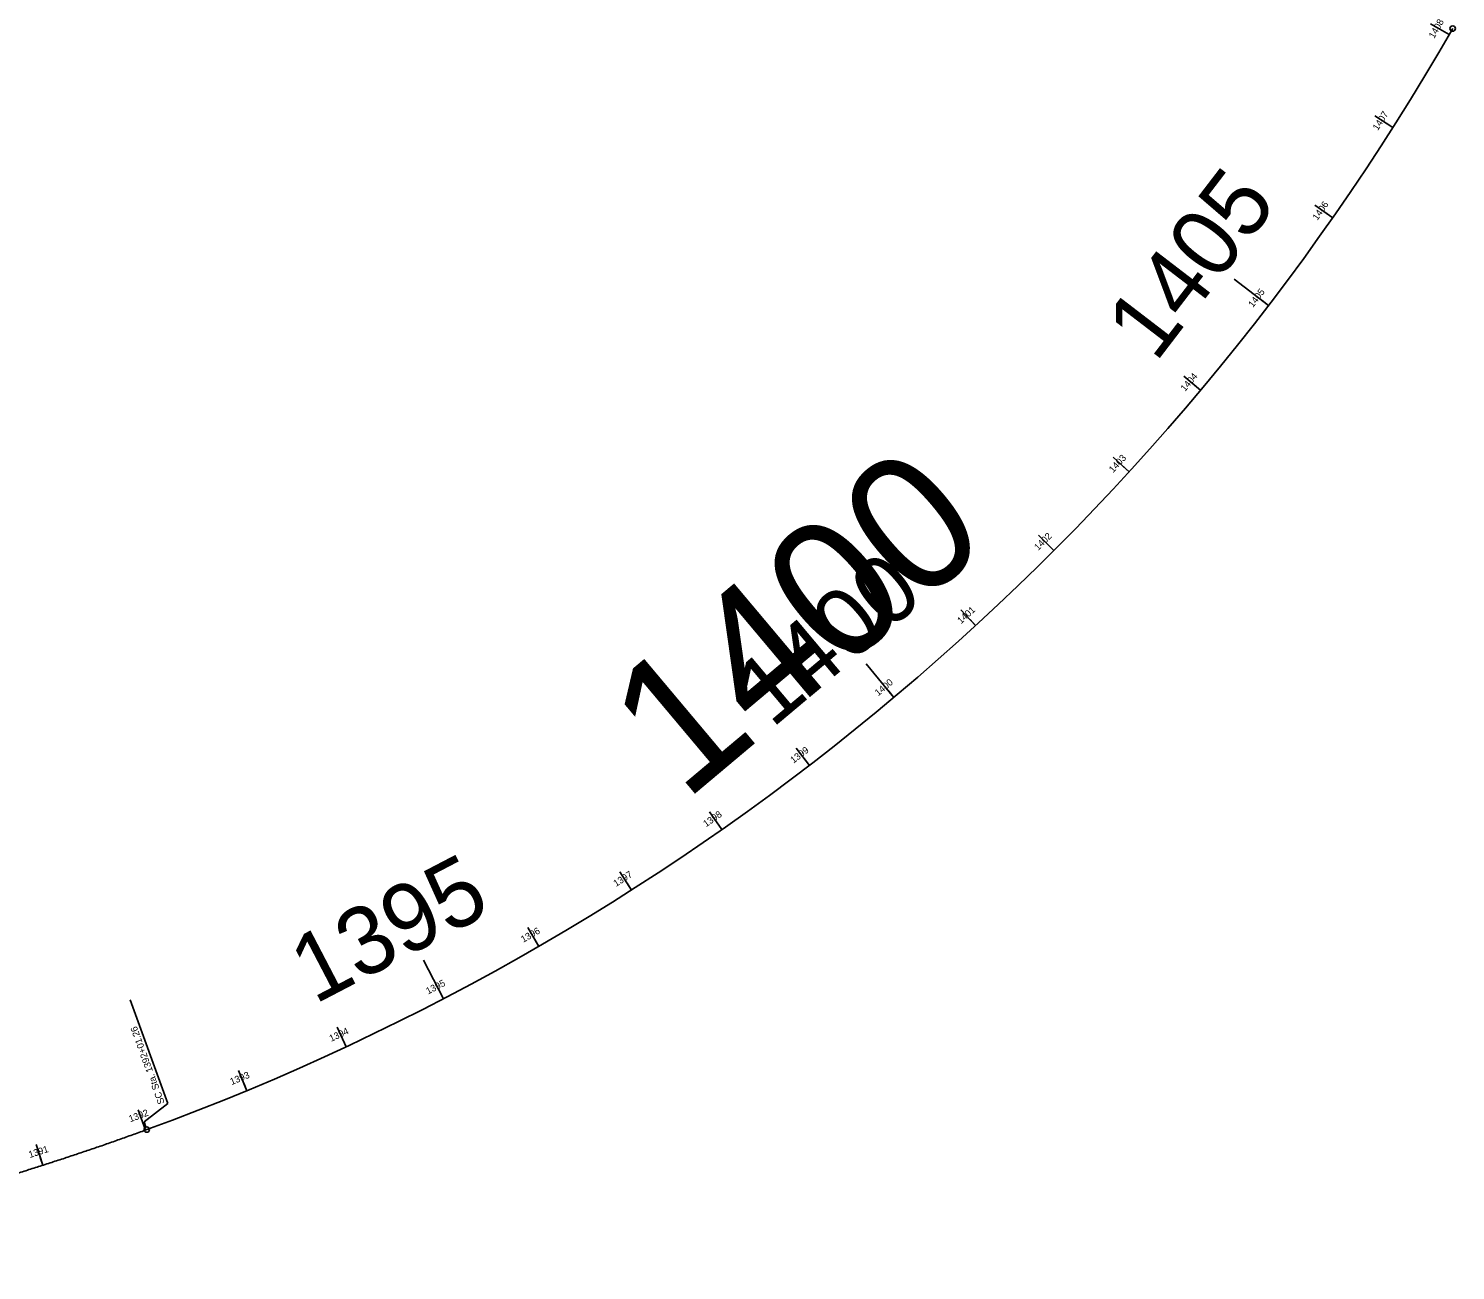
# Model space of a CAD drawing. Extents: x 1281433 to 1457183, y 526241 to 603611.
# Drawn here: x 1397548 to 1398861, y 573059 to 574202 of the extents above; entities that cross this region are included whole.
import ezdxf

# ---------------------------------------------------------------- set-up
doc = ezdxf.new("R2010")
doc.units = 0
for name, color, linetype in [('Level 20', 7, 'Continuous'), ('Level 21', 7, 'Continuous'), ('Level 22', 7, 'Continuous'), ('Level 4', 7, 'Continuous'), ('Level 6', 7, 'Continuous'), ('Level 7', 7, 'Continuous')]:
    doc.layers.add(name, color=color, linetype=linetype)

msp = doc.modelspace()

# ---------------------------------------------------------------- linework, layer by layer
at = {"layer": 'Level 20'}
msp.add_arc((1396870.1, 575341.1), 2291.8, 290.0679, 330.1964, dxfattribs=at)
msp.add_spline([(1397210.2, 573058.8), (1397216.3, 573060.4), (1397222.4, 573061.9), (1397228.5, 573063.5), (1397234.6, 573065), (1397240.6, 573066.6), (1397246.7, 573068.1), (1397252.8, 573069.7), (1397258.9, 573071.2), (1397265, 573072.8), (1397271.1, 573074.4), (1397277.2, 573075.9), (1397283.3, 573077.5), (1397289.3, 573079), (1397295.4, 573080.6), (1397301.5, 573082.2), (1397307.6, 573083.8), (1397313.7, 573085.3), (1397319.8, 573086.9), (1397325.8, 573088.5), (1397331.9, 573090.1), (1397338, 573091.7), (1397344.1, 573093.3), (1397350.1, 573094.9), (1397356.2, 573096.5), (1397362.3, 573098.1), (1397368.4, 573099.7), (1397374.4, 573101.4), (1397380.5, 573103), (1397386.6, 573104.6), (1397392.6, 573106.3), (1397398.7, 573107.9), (1397404.8, 573109.6), (1397410.8, 573111.3), (1397416.9, 573112.9), (1397422.9, 573114.6), (1397429, 573116.3), (1397435, 573118), (1397441.1, 573119.7), (1397447.1, 573121.4), (1397453.2, 573123.1), (1397459.2, 573124.9), (1397465.2, 573126.6), (1397471.3, 573128.4), (1397477.3, 573130.1), (1397483.3, 573131.9), (1397489.4, 573133.7), (1397495.4, 573135.5), (1397501.4, 573137.3), (1397507.4, 573139.1), (1397513.4, 573140.9), (1397519.5, 573142.7), (1397525.5, 573144.6), (1397531.5, 573146.4), (1397537.5, 573148.3), (1397543.5, 573150.2), (1397549.5, 573152.1), (1397555.4, 573154), (1397561.4, 573155.9), (1397567.4, 573157.8), (1397573.4, 573159.8), (1397579.4, 573161.7), (1397585.3, 573163.7), (1397591.3, 573165.7), (1397597.2, 573167.7), (1397603.2, 573169.7), (1397609.1, 573171.7), (1397615.1, 573173.7), (1397621, 573175.8), (1397627, 573177.9), (1397632.9, 573180), (1397638.8, 573182.1), (1397644.7, 573184.2), (1397650.6, 573186.3), (1397656.5, 573188.5)], degree=3, dxfattribs=at)
at = {"layer": 'Level 21'}
msp.add_arc((1396870.1, 575341.1), 2291.8, 290.0679, 330.1964, dxfattribs=at)
msp.add_spline([(1397210.2, 573058.8), (1397216.3, 573060.4), (1397222.4, 573061.9), (1397228.5, 573063.5), (1397234.6, 573065), (1397240.6, 573066.6), (1397246.7, 573068.1), (1397252.8, 573069.7), (1397258.9, 573071.2), (1397265, 573072.8), (1397271.1, 573074.4), (1397277.2, 573075.9), (1397283.3, 573077.5), (1397289.3, 573079), (1397295.4, 573080.6), (1397301.5, 573082.2), (1397307.6, 573083.8), (1397313.7, 573085.3), (1397319.8, 573086.9), (1397325.8, 573088.5), (1397331.9, 573090.1), (1397338, 573091.7), (1397344.1, 573093.3), (1397350.1, 573094.9), (1397356.2, 573096.5), (1397362.3, 573098.1), (1397368.4, 573099.7), (1397374.4, 573101.4), (1397380.5, 573103), (1397386.6, 573104.6), (1397392.6, 573106.3), (1397398.7, 573107.9), (1397404.8, 573109.6), (1397410.8, 573111.3), (1397416.9, 573112.9), (1397422.9, 573114.6), (1397429, 573116.3), (1397435, 573118), (1397441.1, 573119.7), (1397447.1, 573121.4), (1397453.2, 573123.1), (1397459.2, 573124.9), (1397465.2, 573126.6), (1397471.3, 573128.4), (1397477.3, 573130.1), (1397483.3, 573131.9), (1397489.4, 573133.7), (1397495.4, 573135.5), (1397501.4, 573137.3), (1397507.4, 573139.1), (1397513.4, 573140.9), (1397519.5, 573142.7), (1397525.5, 573144.6), (1397531.5, 573146.4), (1397537.5, 573148.3), (1397543.5, 573150.2), (1397549.5, 573152.1), (1397555.4, 573154), (1397561.4, 573155.9), (1397567.4, 573157.8), (1397573.4, 573159.8), (1397579.4, 573161.7), (1397585.3, 573163.7), (1397591.3, 573165.7), (1397597.2, 573167.7), (1397603.2, 573169.7), (1397609.1, 573171.7), (1397615.1, 573173.7), (1397621, 573175.8), (1397627, 573177.9), (1397632.9, 573180), (1397638.8, 573182.1), (1397644.7, 573184.2), (1397650.6, 573186.3), (1397656.5, 573188.5)], degree=3, dxfattribs=at)
at = {"layer": 'Level 22'}
msp.add_arc((1396870.1, 575341.1), 2291.8, 290.0679, 330.1964, dxfattribs=at)
msp.add_spline([(1397210.2, 573058.8), (1397216.3, 573060.4), (1397222.4, 573061.9), (1397228.5, 573063.5), (1397234.6, 573065), (1397240.6, 573066.6), (1397246.7, 573068.1), (1397252.8, 573069.7), (1397258.9, 573071.2), (1397265, 573072.8), (1397271.1, 573074.4), (1397277.2, 573075.9), (1397283.3, 573077.5), (1397289.3, 573079), (1397295.4, 573080.6), (1397301.5, 573082.2), (1397307.6, 573083.8), (1397313.7, 573085.3), (1397319.8, 573086.9), (1397325.8, 573088.5), (1397331.9, 573090.1), (1397338, 573091.7), (1397344.1, 573093.3), (1397350.1, 573094.9), (1397356.2, 573096.5), (1397362.3, 573098.1), (1397368.4, 573099.7), (1397374.4, 573101.4), (1397380.5, 573103), (1397386.6, 573104.6), (1397392.6, 573106.3), (1397398.7, 573107.9), (1397404.8, 573109.6), (1397410.8, 573111.3), (1397416.9, 573112.9), (1397422.9, 573114.6), (1397429, 573116.3), (1397435, 573118), (1397441.1, 573119.7), (1397447.1, 573121.4), (1397453.2, 573123.1), (1397459.2, 573124.9), (1397465.2, 573126.6), (1397471.3, 573128.4), (1397477.3, 573130.1), (1397483.3, 573131.9), (1397489.4, 573133.7), (1397495.4, 573135.5), (1397501.4, 573137.3), (1397507.4, 573139.1), (1397513.4, 573140.9), (1397519.5, 573142.7), (1397525.5, 573144.6), (1397531.5, 573146.4), (1397537.5, 573148.3), (1397543.5, 573150.2), (1397549.5, 573152.1), (1397555.4, 573154), (1397561.4, 573155.9), (1397567.4, 573157.8), (1397573.4, 573159.8), (1397579.4, 573161.7), (1397585.3, 573163.7), (1397591.3, 573165.7), (1397597.2, 573167.7), (1397603.2, 573169.7), (1397609.1, 573171.7), (1397615.1, 573173.7), (1397621, 573175.8), (1397627, 573177.9), (1397632.9, 573180), (1397638.8, 573182.1), (1397644.7, 573184.2), (1397650.6, 573186.3), (1397656.5, 573188.5)], degree=3, dxfattribs=at)
at = {"layer": 'Level 4'}
for p, q in [((1398855.6, 574196.5), (1398838.3, 574206.5)), ((1398803.8, 574111), (1398787, 574121.7)), ((1398748.3, 574027.8), (1398731.9, 574039.3)), ((1398689.3, 573947.1), (1398657.5, 573971.4)), ((1398626.7, 573869.1), (1398611.4, 573881.9)), ((1398560.8, 573793.9), (1398546.1, 573807.4)), ((1398491.7, 573721.6), (1398477.6, 573735.7)), ((1398419.5, 573652.4), (1398406, 573667.1)), ((1398344.4, 573586.4), (1398318.7, 573617.1)), ((1398266.5, 573523.8), (1398254.3, 573539.7)), ((1398185.9, 573464.6), (1398174.4, 573481)), ((1398102.8, 573409), (1398092, 573425.9)), ((1398017.3, 573357.1), (1398007.3, 573374.4)), ((1397929.7, 573308.9), (1397911.2, 573344.4)), ((1397840, 573264.7), (1397831.6, 573282.8)), ((1397748.5, 573224.3), (1397740.9, 573242.8)), ((1397655.4, 573188), (1397648.5, 573206.8)), ((1397560.7, 573155.7), (1397554.6, 573174.7))]:
    msp.add_line(p, q, dxfattribs=at)
at = {"layer": 'Level 6'}
for p, q in [((1398855.6, 574196.5), (1398849.1, 574200.2)), ((1398803.8, 574111), (1398797.5, 574115)), ((1398748.3, 574027.8), (1398742.2, 574032.1)), ((1398689.3, 573947.1), (1398683.3, 573951.7)), ((1398626.7, 573869.1), (1398621, 573873.9)), ((1398560.8, 573793.9), (1398555.3, 573798.9)), ((1398491.7, 573721.6), (1398486.4, 573726.9)), ((1398419.5, 573652.4), (1398414.5, 573657.9)), ((1398344.4, 573586.4), (1398339.6, 573592.2)), ((1398266.5, 573523.8), (1398261.9, 573529.7)), ((1398185.9, 573464.6), (1398181.6, 573470.8)), ((1398102.8, 573409), (1398098.7, 573415.3)), ((1398017.3, 573357.1), (1398013.6, 573363.6)), ((1397929.7, 573308.9), (1397926.2, 573315.6)), ((1397675.9, 573212.6), (1397641.2, 573307.8)), ((1397840, 573264.7), (1397836.9, 573271.4)), ((1397748.5, 573224.3), (1397745.7, 573231.3)), ((1397653.9, 573195.6), (1397675.9, 573212.6)), ((1397655.4, 573188), (1397652.8, 573195.1)), ((1397655.7, 573190.8), (1397653.9, 573195.6)), ((1397560.7, 573155.7), (1397558.4, 573162.8))]:
    msp.add_line(p, q, dxfattribs=at)
for centre in [(1398858.8, 574202), (1397656.5, 573188.5)]:
    msp.add_circle(centre, 2.5, dxfattribs=at)
at = {"layer": 'Level 7'}
for p, q in [((1398689.3, 573947.1), (1398657.5, 573971.4)), ((1398344.4, 573586.4), (1398318.7, 573617.1)), ((1397929.7, 573308.9), (1397911.2, 573344.4))]:
    msp.add_line(p, q, dxfattribs=at)

# ---------------------------------------------------------------- texts
at = {"layer": 'Level 4'}
for s, rotation, p in [('1405', 52.5365, (1398585.3, 573893.7)), ('1400', 40.0365, (1398231.9, 573557.2)), ('1395', 27.5365, (1397810.9, 573303.4))]:
    msp.add_text(s, height=62.4, rotation=rotation, dxfattribs=at).set_placement(p)
at = {"layer": 'Level 6'}
for s, rotation, p in [('1408', 60.0365, (1398841.7, 574192.4)), ('1407', 57.5365, (1398789.9, 574107.7)), ('1406', 55.0365, (1398734.2, 574025)), ('1405', 52.5365, (1398674.9, 573944.8)), ('1404', 50.0365, (1398612.4, 573867.5)), ('1403', 47.5365, (1398546.2, 573792.7)), ('1402', 45.0365, (1398477.1, 573721.1)), ('1401', 42.5365, (1398406.1, 573653.6)), ('1400', 40.0365, (1398329.9, 573587.3)), ('1399', 37.5365, (1398251.9, 573525.3)), ('1398', 35.0365, (1398171.4, 573466.7)), ('1397', 32.5365, (1398088.5, 573411.8)), ('1396', 30.0365, (1398003.1, 573360.4)), ('1395', 27.5365, (1397915.5, 573312.8)), ('SC Sta. 1392+01.26', 110.0679, (1397673, 573213.2)), ('1394', 25.0365, (1397826.2, 573269.2)), ('1393', 22.5365, (1397734.6, 573229.4)), ('1392', 20.0365, (1397641.2, 573195.2)), ('1391', 17.8121, (1397548.8, 573162.3))]:
    msp.add_text(s, height=6.25, rotation=rotation, dxfattribs=at).set_placement(p)
at = {"layer": 'Level 7'}
msp.add_text('1400', height=125, rotation=40.0365, dxfattribs=at).set_placement((1398151.4, 573489.5))

doc.saveas('drawing.dxf')
